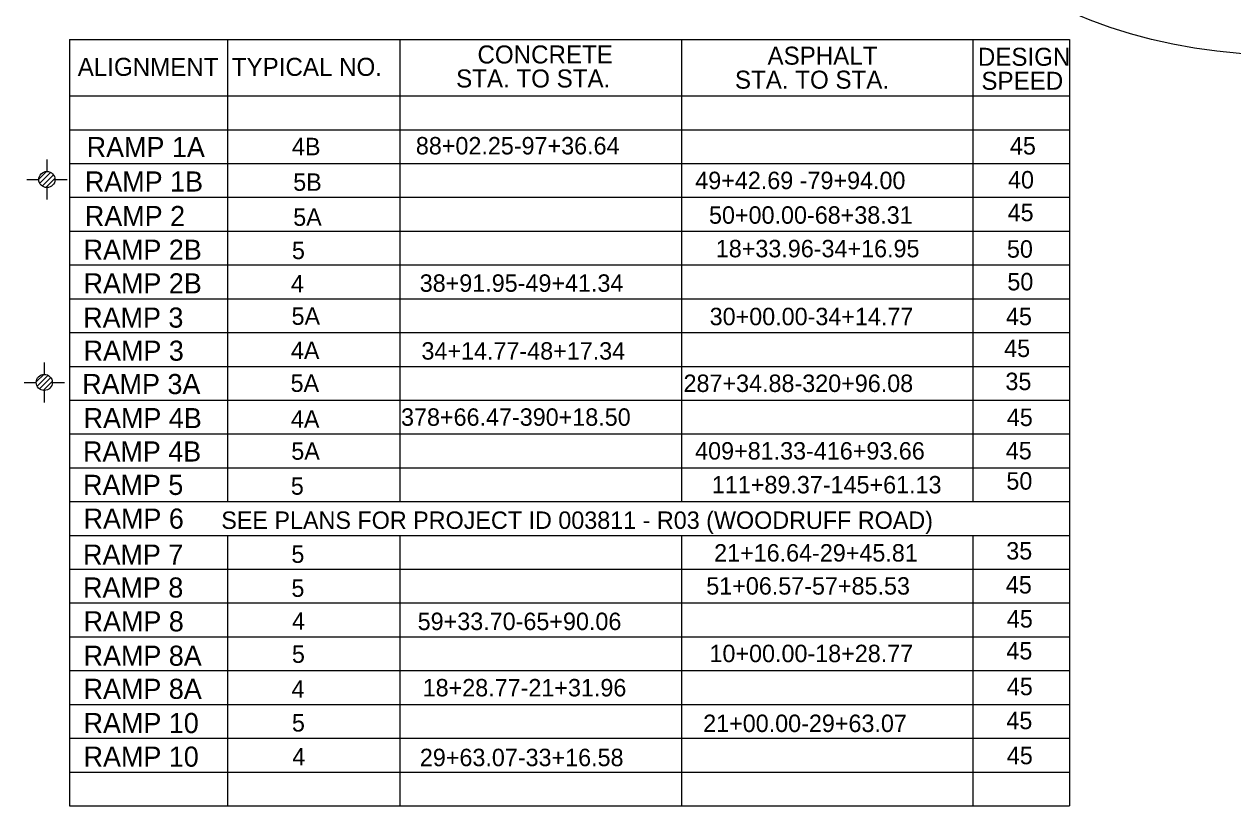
# Model space of a CAD drawing. Extents: x 4932 to 5887, y 4809 to 5473.
# Drawn here: x 5127 to 5206.1, y 5117.3 to 5168.5 of the extents above; entities that cross this region are included whole.
import ezdxf

# ---------------------------------------------------------------- set-up
doc = ezdxf.new("R2010")
doc.units = 0
for name, color, linetype in [('Level 3', 7, 'Continuous'), ('Level 40', 7, 'Continuous'), ('RD_EX_SU_Pole', 7, 'Continuous'), ('RD_TX_TypSect', 7, 'Continuous')]:
    doc.layers.add(name, color=color, linetype=linetype)

# ---------------------------------------------------------------- blocks, each defined once
blk = doc.blocks.new('SUE_TFP')
at = {"layer": 'RD_EX_SU_Pole'}
for p, q in [((0, 5.5), (0, 2.22)), ((-2.21, 0.13), (-0.13, 2.21)), ((-1.96, -1.03), (1.03, 1.96)), ((-1.31, -1.79), (1.79, 1.31)), ((-0.3, -2.2), (2.2, 0.3)), ((2.22, 0), (5.53, 0.01)), ((-5.53, -0.01), (-2.22, 0)), ((0, -2.22), (0, -5.5))]:
    blk.add_line(p, q, dxfattribs=at)
blk.add_circle((0, 0), 2.22, dxfattribs=at)

msp = doc.modelspace()

# ---------------------------------------------------------------- linework, layer by layer
at = {"layer": 'Level 40'}
for p, q in [((5129.958, 5167.512), (5195.45, 5167.512)), ((5129.958, 5167.512), (5129.958, 5163.82)), ((5140.304, 5167.512), (5140.304, 5163.82)), ((5151.589, 5167.512), (5151.589, 5163.82)), ((5170.032, 5167.512), (5170.032, 5163.82)), ((5189.119, 5167.512), (5189.119, 5163.82)), ((5195.45, 5167.512), (5195.45, 5163.82)), ((5129.958, 5163.82), (5195.45, 5163.82)), ((5151.589, 5163.82), (5151.589, 5137.237)), ((5170.032, 5163.82), (5170.032, 5137.237)), ((5189.119, 5163.82), (5189.119, 5137.237)), ((5151.589, 5135.022), (5151.589, 5117.301)), ((5170.032, 5135.022), (5170.032, 5117.301)), ((5189.119, 5135.022), (5189.119, 5117.301))]:
    msp.add_line(p, q, dxfattribs=at)
at = {"layer": 'RD_TX_TypSect'}
for p, q in [((5129.958, 5163.82), (5129.958, 5117.301)), ((5140.304, 5163.82), (5140.304, 5137.237)), ((5195.45, 5163.82), (5195.45, 5117.301)), ((5129.958, 5161.605), (5195.45, 5161.605)), ((5129.958, 5159.389), (5195.45, 5159.389)), ((5129.958, 5157.174), (5195.45, 5157.174)), ((5129.958, 5154.959), (5195.45, 5154.959)), ((5129.958, 5152.744), (5195.45, 5152.744)), ((5129.958, 5150.529), (5195.45, 5150.529)), ((5129.958, 5148.313), (5195.45, 5148.313)), ((5129.958, 5146.097), (5195.45, 5146.097)), ((5129.958, 5143.881), (5195.45, 5143.881)), ((5129.958, 5141.668), (5195.45, 5141.668)), ((5129.958, 5139.453), (5195.45, 5139.453)), ((5129.958, 5137.237), (5195.45, 5137.237)), ((5129.958, 5135.022), (5195.45, 5135.022)), ((5140.304, 5135.022), (5140.304, 5117.301)), ((5129.958, 5132.807), (5195.45, 5132.807)), ((5129.958, 5130.592), (5195.45, 5130.592)), ((5129.958, 5128.377), (5195.45, 5128.377)), ((5129.958, 5126.161), (5195.45, 5126.161)), ((5129.958, 5123.945), (5195.45, 5123.945)), ((5129.958, 5121.729), (5195.45, 5121.729)), ((5129.958, 5119.516), (5195.45, 5119.516)), ((5129.958, 5117.301), (5195.45, 5117.301))]:
    msp.add_line(p, q, dxfattribs=at)
msp.add_ellipse((5209.58, 5189.865), major_axis=(-29.478, 0), ratio=0.793631, dxfattribs=at)

# ---------------------------------------------------------------- block references
at = {"layer": 'Level 3', "xscale": 0.23799999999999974, "yscale": 0.23799999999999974}
for p in [(5128.481, 5158.336), (5128.308, 5145.044)]:
    msp.add_blockref('SUE_TFP', p, dxfattribs=at)

# ---------------------------------------------------------------- texts
at = {"layer": 'RD_TX_TypSect'}
for s, height, p in [('CONCRETE', 1.1814, (5156.677, 5165.941)), ('ASPHALT', 1.1814, (5175.668, 5165.862)), ('DESIGN', 1.1814, (5189.444, 5165.789)), ('ALIGNMENT', 1.1814, (5130.5, 5165.13)), ('TYPICAL NO.', 1.18144, (5140.59, 5165.13)), ('STA. TO STA.', 1.18144, (5155.278, 5164.369)), ('STA. TO STA.', 1.18144, (5173.535, 5164.29)), ('SPEED', 1.1814, (5189.676, 5164.217)), ('RAMP 1A', 1.318, (5131.086, 5159.808)), ('88+02.25-97+36.64', 1.1424, (5152.641, 5159.982)), ('45', 1.1424, (5191.542, 5159.977)), ('4B', 1.1424, (5144.527, 5159.929)), ('RAMP 1B', 1.318, (5130.967, 5157.551)), ('5B', 1.1424, (5144.61, 5157.6)), ('49+42.69 -79+94.00', 1.1424, (5170.939, 5157.709)), ('40', 1.1424, (5191.417, 5157.754)), ('RAMP 2', 1.318, (5130.967, 5155.288)), ('5A', 1.1424, (5144.61, 5155.306)), ('50+00.00-68+38.31', 1.1424, (5171.837, 5155.442)), ('45', 1.1424, (5191.394, 5155.609)), ('RAMP 2B', 1.318, (5130.883, 5153.081)), ('5', 1.142, (5144.526, 5153.123)), ('18+33.96-34+16.95', 1.1424, (5172.282, 5153.242)), ('50', 1.1424, (5191.345, 5153.217)), ('RAMP 2B', 1.318, (5130.883, 5150.877)), ('4', 1.142, (5144.46, 5150.94)), ('38+91.95-49+41.34', 1.1424, (5152.894, 5150.982)), ('50', 1.1424, (5191.374, 5151.075)), ('RAMP 3', 1.318, (5130.856, 5148.633)), ('5A', 1.1424, (5144.5, 5148.819)), ('30+00.00-34+14.77', 1.1424, (5171.879, 5148.792)), ('45', 1.1424, (5191.283, 5148.797)), ('RAMP 3', 1.318, (5130.883, 5146.465)), ('4A', 1.1424, (5144.46, 5146.57)), ('34+14.77-48+17.34', 1.1424, (5153.008, 5146.537)), ('45', 1.1424, (5191.166, 5146.708)), ('RAMP 3A', 1.318, (5130.794, 5144.28)), ('5A', 1.1424, (5144.438, 5144.425)), ('287+34.88-320+96.08', 1.1424, (5170.17, 5144.418)), ('35', 1.1424, (5191.248, 5144.541)), ('RAMP 4B', 1.318, (5130.883, 5142.048)), ('4A', 1.1424, (5144.46, 5142.076)), ('378+66.47-390+18.50', 1.1424, (5151.671, 5142.203)), ('45', 1.1424, (5191.339, 5142.186)), ('RAMP 4B', 1.318, (5130.846, 5139.861)), ('5A', 1.1424, (5144.484, 5139.978)), ('409+81.33-416+93.66', 1.1424, (5170.929, 5139.989)), ('45', 1.1424, (5191.272, 5140.006)), ('RAMP 5', 1.318, (5130.848, 5137.672)), ('50', 1.1424, (5191.31, 5138.017)), ('5', 1.142, (5144.454, 5137.686)), ('111+89.37-145+61.13', 1.1424, (5172.026, 5137.773)), ('RAMP 6', 1.318, (5130.883, 5135.461)), ('SEE PLANS FOR PROJECT ID 003811 - R03 (WOODRUFF ROAD)', 1.1424, (5139.9, 5135.446)), ('RAMP 7', 1.318, (5130.848, 5133.104)), ('5', 1.142, (5144.491, 5133.219)), ('21+16.64-29+45.81', 1.1424, (5172.171, 5133.306)), ('35', 1.1424, (5191.302, 5133.44)), ('RAMP 8', 1.318, (5130.848, 5130.948)), ('5', 1.142, (5144.491, 5130.994)), ('51+06.57-57+85.53', 1.1424, (5171.658, 5131.141)), ('45', 1.1424, (5191.275, 5131.214)), ('RAMP 8', 1.318, (5130.883, 5128.733)), ('4', 1.142, (5144.535, 5128.841)), ('59+33.70-65+90.06', 1.1424, (5152.761, 5128.818)), ('45', 1.1424, (5191.339, 5128.981)), ('10+00.00-18+28.77', 1.1424, (5171.87, 5126.715)), ('45', 1.1424, (5191.309, 5126.891)), ('RAMP 8A', 1.318, (5130.883, 5126.478)), ('5', 1.142, (5144.526, 5126.669)), ('RAMP 8A', 1.318, (5130.883, 5124.309)), ('4', 1.142, (5144.497, 5124.382)), ('18+28.77-21+31.96', 1.1424, (5153.087, 5124.471)), ('45', 1.1424, (5191.339, 5124.549)), ('RAMP 10', 1.318, (5130.883, 5122.068)), ('5', 1.142, (5144.526, 5122.168)), ('21+00.00-29+63.07', 1.1424, (5171.456, 5122.136)), ('45', 1.1424, (5191.309, 5122.324)), ('RAMP 10', 1.318, (5130.883, 5119.865)), ('4', 1.142, (5144.556, 5119.959)), ('29+63.07-33+16.58', 1.1424, (5152.903, 5119.9)), ('45', 1.1424, (5191.339, 5120.025))]:
    msp.add_text(s, height=height, dxfattribs=at).set_placement(p)

doc.saveas('drawing.dxf')
